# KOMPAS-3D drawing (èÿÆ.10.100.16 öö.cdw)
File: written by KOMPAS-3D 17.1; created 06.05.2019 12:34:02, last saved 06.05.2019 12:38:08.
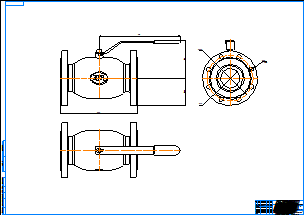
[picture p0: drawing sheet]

Sheet 1: A0, landscape

Title block, sheet 1: name: КШТ.10.100.16 ФФ; material: Внимание! Данный продукт является объектом авторского права ООО «Торговый Дом АДЛ». / Запрещается изменение, копирование, распространение / (в том числе путем копирования на другие сайты и ресурсы в Интернете) / или любое иное использование информации и объектов без предварительного / согласия правообладателя (ООО «Торговый Дом АДЛ»).; sheets: 1; organisation: ООО "Торговый дом АДЛ"; sheet format: A0; stored path: C:\Users\tra\Desktop\2д чертежи\Шаровые краны БИВАЛ\КШ_Бивал_серия_10\KOMPAS 2D\КШТ.10.100.16 ФФ.cdw

Views: Вид 1, Проекционный вид 2, Проекционный вид 3
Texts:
  user
Dimensions and other numbers on the sheet: 148; 107,5; 300; 317; 180; 78; 18; 8 Отв.; 1:1; 1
